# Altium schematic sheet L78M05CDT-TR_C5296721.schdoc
size 127 x 101 mm
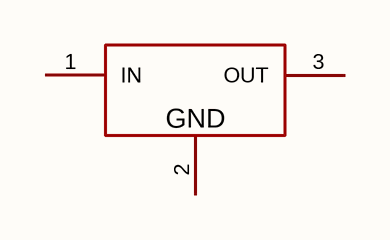
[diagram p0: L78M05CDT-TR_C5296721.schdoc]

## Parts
U?  l78m05cdt-tr(jsm)  [TO-252-3_L6.5-W5.8-P4.58-BL]  (value not drawn)

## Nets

Not connected (* = marked no-connect by the designer): U? 1(IN) 2(GND) 3(OUT)

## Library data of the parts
U? = l78m05cdt-tr(jsm): 输出极性:正极;工作电压:36V;输出电压:5V;输出电流:500mA;电源纹波抑制比(PSRR):80dB@(120Hz);输出类型:固定;; Manufacturer: JSMSEMI(杰盛微); Symbol: L78M05CDT-TR_C5296721; AddInBom: yes; ModelId: b30bfce30d0f4a429b5e4d5ada8cad65; ModelTransform: 249.9995,380.57715,0,0,0,0,0,38.779,0; Output Configuration: 正极; Voltage - Supply: 36V; Output Voltage: 5V; Output Current: 500mA; Voltage Dropout: 1.8V@(250mA); standby current: 4mA; Noise: 40uV; Output Type: 固定; Number of Outputs: 1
